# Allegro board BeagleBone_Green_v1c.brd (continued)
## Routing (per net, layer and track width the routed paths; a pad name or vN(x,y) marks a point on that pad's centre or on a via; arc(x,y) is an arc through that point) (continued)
LCD_DATA8: length 23.7
  TOP w0.121: U5.U1 52.71,35.21 53.34,35.84 53.34,36.58 v1(53.59,36.83)
  LYR3 w0.133: v1(53.59,36.83) 53.9,36.83 54.48,37.41 56.08,37.41 61.34,42.67 63.37,42.67 63.63,42.93 63.63,44.16 63.93,44.46 63.93,45.67 v1(63.86,45.75)
  BOTTOM w0.121: R87.1 64.14,45.47 v1(63.86,45.75) 63.63,45.97 63.63,46.99 R62.2 64.14,48.9 P8.37
LCD_DATA9: length 26.9
  TOP w0.121: v1(53.59,37.47) 53.09,36.96 53.09,35.97 52.73,35.61 52.36,35.61 51.96,35.21 U5.U2
  LYR3 w0.133: v1(63.53,44.63) 63,44.11 61.31,44.11 60.6,43.4 60.6,42.32 56.01,37.72 54.23,37.72 53.98,37.47 v1(53.59,37.47)
  BOTTOM w0.121: P8.38 64.26,51.56 64.26,49.5 62.87,48.11 R61.2 63.37,46.99 63.37,45.59 R86.1 63.32,44.63 v1(63.53,44.63)
LCD_DATA10: length 26.5
  TOP w0.121: v1(52.22,37.52) 52.12,37.41 52.12,35.85 51.88,35.61 51.32,35.61 U5.U3
  LYR3 w0.133: v1(52.22,37.52) 52.69,37.99 55.89,37.99 60.33,42.42 60.33,44.32 v1(61.75,45.75)
  BOTTOM w0.121: R85.1 61.98,45.52 v1(61.75,45.75) 61.47,46.02 61.47,46.99 R60.2 61.98,47.75 63.88,49.66 63.88,51.69 P8.36
LCD_DATA11: length 25
  TOP w0.121: v1(56.26,48.39) R84.1 ; v1(51.18,37.21) 50.52,36.55 50.52,35.61 U5.U4
  LYR3 w0.133: v1(56.26,48.39) 55.63,47.75 54.23,47.75 51.87,45.39 51.87,38.96 51.41,38.51 51.41,37.44 v1(51.18,37.21)
  BOTTOM w0.121: P8.34 60.07,52.7 58.67,51.31 57.28,51.31 56.77,50.8 56.77,48.9 v1(56.26,48.39) R84.1
LCD_DATA12: length 24.3
  TOP w0.121: v1(52.2,38.2) 51.72,37.72 U5.V2
  LYR3 w0.133: v1(61.09,45.8) 60.45,45.16 59.16,45.16 58.95,44.96 53.09,44.96 52.59,44.46 52.59,38.6 v1(52.2,38.2)
  BOTTOM w0.121: P8.35 60.71,48.01 R58.2 61.21,46.99 61.21,45.92 v1(61.09,45.8) 60.71,45.42 R83.1
LCD_DATA13: length 22.5
  TOP w0.121: v1(51.23,36.55) 50.92,36.24 U5.V3
  LYR3 w0.133: v1(59.39,45.77) 59,45.77 58.44,45.21 52.83,45.21 52.12,44.5 52.12,38.73 51.74,38.35 51.74,37.06 v1(51.23,36.55)
  BOTTOM w0.121: R82.1 59.82,45.34 v1(59.39,45.77) 59.31,45.85 59.31,46.99 R57.2 59.82,49.66 P8.33
LCD_DATA14: length 19.3
  TOP w0.121: P8.31 56.77,49.15 53.98,49.15 53.59,48.77 53.59,48.13 R56.2 52.58,47.12 52.58,45.21 52.96,44.83 R81.1 52.32,43.81 52.32,43.05 51.94,42.67 51.94,38.86 50.12,37.04 U5.V4
LCD_DATA15: length 24.4
  TOP w0.121: v1(49.72,34.81) U5.T5 ; v1(54.23,48.51) 53.98,48.26 R80.1
  LYR3 w0.133: v1(49.72,34.81) 49.72,36.77 50.8,37.85 50.8,43.31 51.63,44.14 51.63,45.49 54.23,48.08 v1(54.23,48.51)
  BOTTOM w0.121: P8.32 57.66,52.7 56.52,51.56 56.52,49.66 56.01,49.15 54.86,49.15 v1(54.23,48.51) R55.2
LCD_DE: length 15.3
  TOP w0.121: 55.24,52.7 53.85,51.31 52.07,51.31 51.56,50.8 51.56,48.51 50.42,47.37 50.42,45.09 50.8,44.7 50.8,42.93 50.16,42.29 R48.2
LCD_HSYNC: length 11.5
  TOP w0.121: 55.24,50.16 54.1,50.16 52.14,48.2 52.14,46.04 52.07,45.97 52.07,43.18 51.44,42.55 R47.2
LCD_PCLK: length 9.3
  TOP w0.121: P8.28 51.18,51.18 51.18,48.67 50.16,47.65 R45.2
LCD_VSYNC: length 6.6
  TOP w0.121: R46.2 51.44,45.59 51.05,45.97 51.05,47.5 52.7,49.15 P8.27
LCDDE: length 6.9
  TOP w0.121: R48.1 v1(50.16,39.12) ; v1(48.92,34.01) U5.R6
  LYR3 w0.121: 49.32,35.18 49.32,34.41 v1(48.92,34.01)
  LYR3 w0.133: v1(50.16,39.12) 49.4,38.35 49.4,37.72 49.32,37.64 49.32,35.18
LCDPCLK: length 7.8
  TOP w0.121: R45.1 50.16,42.8 49.66,42.29 49.66,37.55 49.32,37.21 U5.V5
LCDVHYNC: length 7.1
  TOP w0.121: v1(51.44,39.12) R47.1 ; v1(49.72,34.01) U5.R5
  LYR3 w0.121: v1(49.72,34.01) 50.12,34.41 50.12,35.13
  LYR3 w0.133: 50.12,35.13 50.12,36.79 51.08,37.74 51.08,38.76 v1(51.44,39.12)
LCDVSYNC: length 9.1
  TOP w0.121: R46.1 51.44,42.93 50.71,42.21 50.71,38.01 49.72,37.02 49.72,35.61 U5.U5
LDO_PGOOD: length 35.6
  TOP w0.121: U2.46 21.46,18.99 v1(20.83,19.62) ; U5.B5 v1(49.72,22.81)
  LYR3 w0.133: v1(49.72,22.81) 49.72,20.51 49.4,20.19 47.35,20.19 46.35,19.2 38.18,19.2 37.29,20.09 34.9,20.09 33.53,21.46 27.05,21.46 25.91,20.32 21.53,20.32 v1(20.83,19.62)
LEDAA: length 6.3
  TOP w0.381: D2.2 6.48,49.02 6.86,48.64 6.86,48.26 7.37,47.75 11.18,47.75 R72.2
LEDAC: length 17.4
  TOP w0.121: v1(18.54,45.59) 19.05,45.59 19.29,45.35 Q1.6 ; D2.1 4.13,48.7 4.7,48.13 v1(6.22,48.13)
  LYR3 w0.133: v1(18.54,45.59) 16.64,47.5 6.86,47.5 v1(6.22,48.13)
LEDBA: length 5.7
  TOP w0.381: D3.2 6.29,46.74 R73.2
LEDBC: length 22.1
  TOP w0.121: Q1.3 20.59,43.58 20.83,43.81 v1(21.21,43.81) ; v1(3.3,48.26) 4.13,47.43 D3.1
  LYR3 w0.133: v1(3.3,48.26) 4.45,47.12 15.11,47.12 18.41,43.81 v1(21.21,43.81)
LEDCA: length 5.9
  TOP w0.381: R74.2 7.62,45.85 6.73,44.96 D4.2
LEDCC: length 13.8
  TOP w0.121: v1(15.62,45.59) 16,45.21 16.51,45.21 16.62,45.1 Q2.6 ; D4.1 4.13,45.02 v1(5.33,46.23)
  LYR3 w0.133: v1(15.62,45.59) 14.99,46.23 v1(5.33,46.23)
LEDDA: length 6.4
  TOP w0.381: D5.2 5.97,43.18 7.87,45.09 11.18,45.09 R71.2
LEDDC: length 19.1
  TOP w0.121: D5.1 4.06,43.18 v1(3.3,43.94) ; v1(18.54,42.47) 18.47,42.47 17.92,43.01 Q2.3
  LYR3 w0.133: v1(3.3,43.94) 4.47,45.11 15.9,45.11 v1(18.54,42.47)
MDIO_CLK: length 14.5
  TOP w0.121: U14.17 26.83,34.17 26.95,34.29 28.7,34.29 28.83,34.16 32,34.16 32.51,34.67 33.4,34.67 35.31,32.77 35.69,32.77 36.7,31.75 37.72,31.75 38.35,31.11 38.82,31.11 U5.M18
MDIO_DATA: length 15
  TOP w0.121: U5.M17 39.32,30.81 38.28,30.81 37.59,31.5 36.58,31.5 35.56,32.51 35.18,32.51 33.38,34.31 32.66,34.31 32.26,33.91 32.26,33.46 31.97,33.18 30.45,33.18 R119.2 29.34,33.66 28.83,33.15 28.32,33.15 28.04,32.87 U14.16
MII1_COL: length 24.2
  TOP w0.121: v1(40.12,27.61) U5.H16
  LYR3 w0.133: v1(31.75,26.04) 31.11,26.04 30.99,25.91 30.99,25.27 30.86,25.15 29.84,25.15 29.72,25.27 29.72,26.42 29.84,26.54 32.38,26.54 32.51,26.67 32.51,27.81 32.64,27.94 39.79,27.94 v1(40.12,27.61)
  BOTTOM w0.121: R138.1 31.43,32.26 31.84,32.26 32.15,31.95 32.15,30.84 32.51,30.48 32.51,26.8 v1(31.75,26.04)
MII1_CRS_DV: length 25.6
  TOP w0.121: v1(36.83,28.41) 39.32,28.41 U5.H17 ; R139.1 v1(31.75,32.7)
  BOTTOM w0.121: v1(31.75,32.7) 31.75,33.05 31.85,33.15 32.3,33.15 32.4,33.05 32.4,31.09 32.5,30.99 34.95,30.99 35.05,30.89 35.05,30.77 34.95,30.67 32.96,30.67 32.86,30.57 32.86,30.45 32.96,30.35 35.81,30.35 36.07,30.1 36.07,24.49 36.17,24.38 36.33,24.38 36.43,24.49 36.43,28.01 v1(36.83,28.41)
MII1_REFCLK: length 18.5
  TOP w0.121: R28.2 33.78,27.43 33.91,27.3 34.98,27.3 35.08,27.2 35.08,27.03 34.98,26.92 33.86,26.92 33.78,26.85 33.78,26.62 33.86,26.54 34.98,26.54 35.05,26.47 35.05,26.24 34.98,26.16 33.86,26.16 33.78,26.09 33.78,25.86 33.91,25.73 34.21,25.73 34.3,25.64 34.3,25.47 34.17,25.35 33.88,25.35 33.78,25.25 33.78,24.97 33.71,24.89 32.59,24.89 32.51,24.97 32.51,25.2 32.59,25.27 33.32,25.27 33.4,25.35 33.4,25.58 33.32,25.65 32.59,25.65 32.51,25.73 32.51,25.94 32.59,26.02 33.32,26.02 33.42,26.12 33.42,26.85 33.3,26.97 32.68,26.97 32.46,26.75 32.46,26.62 32.33,26.49 32.2,26.49 32.11,26.58 32.11,26.95 32,27.05 31.81,27.05 v1(31.75,26.99) 31.69,26.92 R124.1
  BOTTOM w0.121: v1(31.75,26.99) 31.75,26.8 R140.1
MII1_RXCLK: length 23.8
  TOP w0.121: U5.L18 38.3,30.41 37.47,31.24 36.45,31.24 35.43,32.26 35.05,32.26 33.78,33.53 33.53,33.53 33.42,33.42 33.42,33 33.29,32.87 32.26,32.87 32.15,32.77 32.15,32.63 32.28,32.51 32.66,32.51 32.77,32.4 32.77,30.58 32.87,30.48 32.98,30.48 33.08,30.58 33.08,31.78 33.19,31.88 33.36,31.88 33.46,31.78 33.46,29.34 33.34,29.21 32.64,29.21 32.51,29.34 32.51,30.04 32.19,30.35 31.85,30.35 31.75,30.45 v1(31.75,30.8)
  BOTTOM w0.121: v1(31.75,30.8) 32.26,30.29 32.26,27.81 31.88,27.43 31.11,27.43 30.99,27.3 R131.1
MII1_RXD0: length 24.3
  TOP w0.121: v1(31.75,31.75) 31.75,31.56 R128.1 ; U5.M16 40.12,31.61 v1(39.32,31.61)
  LYR3 w0.133: v1(31.75,31.75) 30.96,31.75 30.86,31.85 30.86,35.97 30.96,36.07 32.28,36.07 32.38,35.97 32.38,35.15 32.28,35.05 31.37,35.05 31.24,34.92 31.24,34.29 31.37,34.16 32.28,34.16 32.38,34.06 32.38,33.25 32.28,33.15 31.37,33.15 31.24,33.02 31.24,32.42 31.37,32.3 32.36,32.3 32.64,32.02 38.91,32.02 v1(39.32,31.61)
MII1_RXD1: length 24.6
  TOP w0.121: R127.1 31.24,30.1 31.5,30.1 v1(31.75,29.84) ; U5.L15 v1(40.92,30.01)
  LYR3 w0.121: v1(40.92,30.01) 40.52,29.61 39.75,29.61
  LYR3 w0.133: v1(31.75,29.84) 31.5,30.1 30.96,30.1 30.1,30.96 30.1,31.88 29.97,32 29.74,32 29.62,31.88 29.62,30.71 30.99,29.34 31.88,29.34 32.16,29.62 32.16,30.12 32.89,30.86 32.89,31.14 32.99,31.24 33.17,31.24 33.27,31.14 33.27,30.71 33.38,30.61 33.55,30.61 33.66,30.71 33.66,31.14 33.76,31.24 33.93,31.24 34.04,31.14 34.04,30.71 34.14,30.61 34.32,30.61 34.42,30.71 34.42,31.14 34.52,31.24 34.7,31.24 34.8,31.14 34.8,30.71 34.9,30.61 35.08,30.61 35.15,30.68 35.15,31.14 35.26,31.24 36.2,31.24 36.32,31.11 36.32,30.51 36.42,30.4 37.11,30.4 37.24,30.53 37.24,30.99 37.33,31.08 37.6,31.08 39.07,29.61 39.75,29.61
MII1_RXD2: length 24.2
  TOP w0.121: R126.1 30.99,29.24 31.09,29.34 31.39,29.34 31.5,29.24 31.5,28.99 31.6,28.89 31.78,28.89 31.88,28.99 31.88,29.36 31.98,29.46 32.16,29.46 32.26,29.36 32.26,28.99 32.36,28.89 33.66,28.89 33.78,29.02 33.78,32.03 33.68,32.13 33.12,32.13 33.02,32.23 33.02,32.41 33.12,32.51 33.55,32.51 33.66,32.61 33.66,32.92 33.76,33.02 33.94,33.02 34.69,32.27 34.69,30.85 34.8,30.73 34.96,30.73 35.07,30.85 35.07,31.91 35.17,32.01 35.31,32.01 35.58,31.74 35.58,31.36 35.68,31.26 36.07,31.26 36.21,31.11 36.21,30.94 36.07,30.8 35.85,30.8 v1(35.84,30.81) ; U5.L16 v1(40.92,30.81)
  BOTTOM w0.121: v1(40.92,30.81) 40.92,30.56 40.77,30.41 39.95,30.41 39.37,29.83 39.37,29.59 39.12,29.34 37.21,29.34 37.01,29.54 36.47,29.54 36.35,29.67 36.35,30.81 36.23,30.93 35.96,30.93 v1(35.84,30.81)
MII1_RXD3: length 24.2
  TOP w0.121: U5.L17 39.72,30.2 39.54,30.01 37.69,30.01 37.59,30.11 37.59,30.76 37.49,30.86 37.31,30.86 37.23,30.78 37.23,30.2 37.13,30.1 36.86,30.1 36.6,30.35 36.35,30.35 36.09,30.1 35.94,30.1 35.69,30.35 34.9,30.35 34.8,30.25 34.8,28.93 34.9,28.83 35.08,28.83 35.18,28.93 35.18,29.17 35.3,29.29 35.38,29.29 35.47,29.2 35.47,28.93 35.57,28.83 35.76,28.83 35.86,28.93 35.86,29.34 35.96,29.45 36.09,29.45 36.18,29.36 36.18,28.66 36.09,28.57 34.52,28.57 34.42,28.68 34.42,32.16 34.32,32.26 34.14,32.26 34.04,32.16 34.04,28.7 33.91,28.57 31.62,28.57 R125.1
MII1_RXDV: length 25.6
  TOP w0.121: U5.J17 v1(40.12,29.21) ; v1(22.66,35.79) 21.95,35.79 R129.1
  LYR3 w0.133: v1(22.66,35.79) 22.78,35.66 22.78,33.91 23.95,32.74 25.37,32.74 28.75,29.36 29.64,29.36 30.33,28.68 31.98,28.68 32.63,29.32 32.63,29.86 32.81,30.05 34.7,30.05 35.33,29.41 35.71,29.41 36.37,30.07 38.23,30.07 38.96,29.34 39.99,29.34 v1(40.12,29.21)
MII1_RXERR: length 24.5
  TOP w0.121: R133.1 30.99,32.14 31.08,32.23 31.4,32.23 31.43,32.26 32.29,32.26 32.39,32.16 32.39,31.76 32.16,31.52 32.16,30.84 33.02,29.97 33.02,29.65 v1(33.03,29.64) ; U5.J15 v1(40.92,29.21)
  LYR3 w0.121: v1(40.92,29.21) 40.52,28.81 39.86,28.81
  LYR3 w0.133: 39.86,28.81 39.47,28.81 39.3,28.98 39.01,28.98 38.91,28.88 38.91,28.57 38.82,28.48 38.55,28.48 38.46,28.57 38.46,29.44 38.33,29.57 38.13,29.57 38.05,29.49 38.05,28.55 37.95,28.46 37.76,28.46 37.59,28.63 37.59,29.39 37.21,29.77 36.55,29.77 36.14,29.36 36.14,28.61 36.01,28.47 35.74,28.47 35.67,28.55 35.67,29.01 35.57,29.11 35.38,29.11 35.28,29.01 35.28,28.57 35.18,28.47 34.96,28.47 34.83,28.61 34.83,29.57 34.71,29.69 34.52,29.69 34.42,29.59 34.42,28.6 34.32,28.5 34.09,28.5 33.96,28.64 33.96,29.62 33.81,29.77 33.63,29.77 33.5,29.64 33.5,28.55 33.41,28.46 33.09,28.46 32.99,28.55 32.99,29.6 v1(33.03,29.64)
MII1_TXCLK: length 22.8
  TOP w0.121: U5.K18 37.47,29.61 37.26,29.82 35.74,29.82 35.64,29.92 v1(35.55,29.92)
  LYR3 w0.133: v1(35.55,29.92) 35.15,30.33 32.72,30.33 32.39,30 32.39,29.5 31.88,28.98 30.84,28.98 29.49,30.33 28.35,30.33 27.74,30.94 27.74,31.34 27.38,31.7 26.85,31.7 26.72,31.83 26.72,32.13 26.8,32.21 27.64,32.21 27.82,32.39 27.82,32.58 27.64,32.77 27.33,32.77 27.23,32.87 27.23,33.12 27.33,33.22 28.19,33.22 v1(28.57,33.6)
  BOTTOM w0.121: v1(28.57,33.6) 28.57,34.62 29.01,35.05 30.48,35.05 R134.1
MII1_TXD0: length 28
  TOP w0.121: v1(24.13,34.61) 24.33,34.41 U14.22 ; U5.K17 39.32,29.21 37.47,29.21 37.19,29.48 36.53,29.48 36.43,29.38 36.43,28.4 36.35,28.32 32.26,28.32 32.15,28.21 32.15,27.61 32,27.46 28.92,27.46 v1(28.45,27.94)
  LYR4 w0.133: v1(28.45,27.94) 27.94,28.45 27.69,28.45 27.33,28.8 27.33,30.23 27.2,30.35 26.7,30.35 26.62,30.43 26.62,30.86 26.72,30.96 27.18,30.96 27.33,31.11 27.33,31.6 27.18,31.75 25.93,31.75 25.81,31.88 25.81,32.2 25.94,32.33 26.52,32.33 26.61,32.42 26.61,32.68 26.26,33.02 24.82,33.02 24.74,33.1 24.74,33.45 24.84,33.55 25.27,33.55 25.39,33.67 25.39,33.9 25.25,34.04 24.7,34.04 v1(24.13,34.61)
MII1_TXD1: length 28
  TOP w0.121: U14.23 23.83,34.27 v1(23.5,34.61) ; v1(40.12,30.01) U5.K16
  LYR3 w0.133: v1(23.5,34.61) 24.07,34.04 25.78,34.04 25.94,33.88 25.94,33.69 25.78,33.53 24.14,33.53 24,33.39 24,33.21 24.1,33.11 26.81,33.11 27.1,33.4 27.1,33.86 27.41,34.16 29.84,34.16 30.35,33.66 30.35,31.11 31.08,30.39 31.92,30.39 32.16,30.63 32.16,30.96 32.69,31.5 37.62,31.5 39.1,30.01 v1(40.12,30.01)
MII1_TXD2: length 28.1
  TOP w0.121: v1(28.45,35.56) 28.19,35.31 23.56,35.31 23.1,34.84 23.1,34.37 23.33,34.14 U14.24 ; U5.K15 v1(41.72,30.01)
  LYR3 w0.121: v1(41.72,30.01) 41.72,30.01 41.32,30.41 39.88,30.41
  LYR3 w0.133: 39.88,30.41 39.08,30.41 37.74,31.75 32.51,31.75 32.03,31.27 30.71,31.27 30.61,31.37 30.61,36.58 30.48,36.7 28.57,36.7 28.45,36.58 v1(28.45,35.56)
MII1_TXD3: length 28.3
  TOP w0.121: v1(35.56,33.27) 33.78,35.05 31.42,35.05 31.29,34.92 31.29,34.62 31.21,34.53 30.79,34.53 30.73,34.59 30.73,35.86 30.63,35.97 30.35,35.97 30.25,35.86 30.25,34.67 30.12,34.54 29.84,34.54 29.72,34.66 29.72,35.74 29.13,36.32 25.35,36.32 24.71,35.69 23.24,35.69 22.38,34.82 22.38,34.32 22.1,34.04 22.1,33.06 22.29,32.87 U14.25 ; v1(36.83,29.08) 36.83,29.06 37.08,28.81 U5.J18
  LYR4 w0.133: v1(36.83,29.08) 36.32,29.59 36.32,32.51 v1(35.56,33.27)
MII1_TXEN: length 28.5
  TOP w0.121: v1(40.12,28.41) U5.J16 ; v1(24.83,34.61) U14.21
  LYR3 w0.133: v1(28.45,28.89) 28.42,28.87 28.42,28.48 28.56,28.35 29.46,28.35 29.67,28.55 30.02,28.55 30.15,28.42 30.15,27 30.24,26.91 30.46,26.91 30.63,27.08 30.63,28.22 30.76,28.35 31.01,28.35 31.19,28.17 31.19,27.57 31.32,27.43 32.03,27.43 32.26,27.66 32.26,28.55 32.41,28.7 32.61,28.7 32.74,28.57 32.74,28.35 32.89,28.19 36.25,28.19 36.4,28.35 36.4,29.26 36.65,29.51 37.01,29.51 37.34,29.18 37.34,28.51 37.66,28.19 37.99,28.19 37.99,28.2 39.9,28.2 39.9,28.19 v1(40.12,28.41)
  LYR4 w0.133: v1(28.45,28.89) 28,28.89 27.76,29.13 27.76,31.95 25.11,34.61 v1(24.83,34.61)
MMC0_CD: length 80.4
  TOP w0.121: v1(40.92,23.61) U5.C15
  LYR3 w0.133: v1(70.1,42.8) 70.1,35.59 71.07,34.62 71.07,19.63 66.73,15.29 55.22,15.29 54.51,16 54.51,17.83 53.21,19.13 52.4,19.13 51.71,19.81 47.4,19.81 46.43,18.85 35.33,18.85 v1(35.15,18.67)
  BOTTOM w0.121: v1(40.92,23.61) 40.52,23.21 40.52,21.84 39.53,20.85 36.09,20.85 35.42,20.18 35.42,19.31 35.15,19.05 v1(35.15,18.67) 34.67,18.67 34.61,18.73 P2.19 ; P10.10 69.98,43.69 69.92,43.63 69.86,43.63 69.47,43.24 R157.1 69.72,43.18 v1(70.1,42.8)
MMC0_CLKO: length 81.6
  TOP w0.121: v1(31.75,20.32) 32.84,21.41 32.84,23.63 35.24,26.04 37.08,26.04 38.66,27.61 39.32,27.61 U5.G17
  LYR3 w0.133: v1(31.75,20.32) 31.74,20.31 31.74,19.29 33.98,17.06 38.55,17.06 39.27,17.78 42.48,17.78 44.99,15.27 46.05,15.27 47.47,13.84 47.47,11.91 48.26,11.12 52.8,11.12 55.83,14.15 68.08,14.15 72.62,18.68 72.62,22.9 77.68,27.97 79.78,27.97 v1(80.24,27.51)
  BOTTOM w0.121: v1(80.24,27.51) 80.67,27.94 R152.2 82.58,29.62 83.21,29.62 83.7,30.1 P10.5
MMC0_CMD: length 92.7
  TOP w0.121: U5.G18 38.64,27.21 37.21,25.78 35.34,25.78 33.15,23.59 33.15,21.08 v1(32.38,20.32) ; R151.2 81.41,42.93 v1(82.17,43.69)
  LYR3 w0.133: v1(82.17,43.69) 82.17,43.56 81.66,43.05 81.66,38.48 72.16,28.98 72.16,18.56 68.05,14.45 55.7,14.45 52.6,11.35 48.36,11.35 47.75,11.96 47.75,14.45 45.14,17.07 44.25,17.07 43.3,18.01 39.18,18.01 38.55,17.39 38.55,17.39 38.45,17.29 34.08,17.29 31.98,19.39 31.98,19.91 v1(32.38,20.32)
  BOTTOM w0.121: v1(82.17,43.69) 83,44.51 P10.3
MMC0_DAT0: length 69.6
  TOP w0.121: v1(40.12,26.81) U5.G16
  LYR3 w0.133: v1(78.99,27.56) 78.23,26.8 77.43,26.8 73.28,22.64 73.28,18.68 68.21,13.61 56.11,13.61 53.14,10.65 48.07,10.65 46.86,11.85 46.86,13.66 45.91,14.61 44.99,14.61 42.68,16.92 40.28,16.92 40.13,16.76 v1(39.7,16.76)
  LYR4 w0.133: v1(40.12,26.81) 39.92,26.81 37.82,24.71 37.82,21.59 38.28,21.13 38.28,18.11 39.62,16.76 v1(39.7,16.76)
  BOTTOM w0.121: v1(78.99,27.56) 79.25,27.56 R153.2 80.52,28.83 81.03,28.83 82.3,30.1 P10.7
MMC0_DAT1: length 68.5
  TOP w0.121: v1(40.92,26.81) U5.G15
  LYR3 w0.133: v1(39.71,17.37) 42.55,17.37 45,14.92 45.93,14.92 47.12,13.73 47.12,11.93 48.17,10.88 53,10.88 55.98,13.87 68.14,13.87 73,18.73 73,22.71 v1(77.72,27.43)
  LYR4 w0.121: 38.07,22.1 38.07,21.88 38.11,21.84 ; v1(39.71,17.37) 38.58,18.5 38.58,21.37 ; 39.74,26.19 39.95,26.41 40.52,26.41 v1(40.92,26.81)
  LYR4 w0.133: 38.58,21.37 38.11,21.84 ; 38.07,22.1 38.07,24.53 39.74,26.19
  BOTTOM w0.121: P10.8 81.6,30.03 80.77,29.21 79.63,29.21 R154.2 78.23,27.94 v1(77.72,27.43)
MMC0_DAT2: length 87.2
  TOP w0.121: R150.2 79.63,42.8 v1(80.52,43.69) ; v1(33.02,19.56) 33.15,19.56 33.42,19.83 33.42,23.51 35.44,25.53 37.34,25.53 38.22,26.41 U5.F18
  LYR3 w0.133: v1(33.02,19.56) 34.57,18.01 35.28,18.01 35.81,18.54 43.56,18.54 44.15,17.96 45.97,17.96 47.45,19.43 51.64,19.43 52.25,18.82 53.11,18.82 54.23,17.7 54.23,15.8 55.04,14.99 66.85,14.99 71.53,19.66 71.53,29.06 80.8,38.33 80.8,43.28 80.52,43.56 v1(80.52,43.69)
  BOTTOM w0.121: P10.1 81.6,44.64 81.15,44.2 81.03,44.2 v1(80.52,43.69)
MMC0_DAT3: length 90.6
  TOP w0.121: U5.F17 39.32,26.01 38.19,26.01 37.47,25.29 35.55,25.29 33.78,23.52 33.78,19.56 33.27,19.05 32.89,19.05 v1(32.38,19.56) ; v1(81.28,43.69) 80.52,42.93 R155.2
  LYR3 w0.133: v1(32.38,19.56) 34.32,17.63 38.46,17.63 39.08,18.25 43.45,18.25 44.35,17.35 45.92,17.35 47.75,19.18 51.44,19.18 52.7,17.91 53.52,17.91 53.98,17.45 53.98,15.65 54.94,14.68 66.88,14.68 71.86,19.66 71.86,29.01 81.28,38.43 v1(81.28,43.69)
  BOTTOM w0.121: P10.2 82.3,44.58 81.41,43.69 v1(81.28,43.69)
MMC1_CLK: length 41.5
  TOP w0.121: U5.U9 46.52,35.61 46.52,35.98 46.52,35.98 46.52,36.17 46.67,36.32 46.67,44.39 45.85,45.21 45.85,49.4 P8.21
  TOP w0.203: v1(28.09,42.49) 28.07,42.47 27.78,42.47 U13.M6
  LYR4 w0.133: v1(28.09,42.49) 28.26,42.49 29.43,41.33 34.49,41.33 36.91,43.74 36.91,44.65 40.01,47.75 43.88,47.75 45.09,48.96 P8.21
  BOTTOM w0.121: R110.2 P8.21
MMC1_CMD: length 43.6
  TOP w0.121: P8.20 43.81,51.44 43.81,49.53 45.59,47.75 45.59,44.96 46.42,44.13 46.42,36.52 46.12,36.21 U5.V9
  TOP w0.203: U13.M5 27.63,43.12 28.03,43.12 v1(28.09,43.05)
  LYR4 w0.133: v1(42.55,48.26) 40.01,48.26 36.65,44.91 36.65,43.84 34.39,41.58 29.68,41.58 28.2,43.05 v1(28.09,43.05)
  BOTTOM w0.121: R109.2 v1(42.55,48.26) 41.4,49.4 41.4,51.56 P8.20
MMC1_DAT0: length 35.5
  TOP w0.121: v1(48.9,48.26) 48.39,47.75 48.39,45.47 47.75,44.83 47.75,39.24 47.76,39.24 47.76,39.14 48.26,38.64 48.26,36.58 48.12,36.44 48.12,35.61 U5.U7 ; v1(38.1,44.96) 37.11,45.95 35.2,45.95 33.42,44.16 U13.A3
  LYR4 w0.133: v1(48.9,48.26) 47.37,46.74 41.27,46.74 39.5,44.96 v1(38.1,44.96)
  BOTTOM w0.121: R101.2 v1(48.9,48.26) 48.9,48.9 P8.25
MMC1_DAT1: length 39.5
  TOP w0.121: P8.24 48.77,51.56 48.77,49.4 48.13,48.77 48.13,45.59 47.5,44.96 47.5,38.99 48.01,38.48 48.01,36.7 47.72,36.42 U5.V7 ; U13.A4 33.65,43.66 34.55,44.56 36.92,44.56 37.03,44.45 38.35,44.45 38.73,44.83 v1(38.73,45.72)
  LYR4 w0.133: v1(46.35,48.26) 45.34,47.24 40.26,47.24 v1(38.73,45.72)
  BOTTOM w0.121: R102.2 v1(46.35,48.26) 46.35,51.44 P8.24
MMC1_DAT2: length 41.4
  TOP w0.121: v1(47.32,34.01) U5.R8 ; U13.A5 34.35,43.16 34.62,43.43 34.62,43.84 34.87,44.09 v1(35.56,44.09)
  LYR3 w0.121: 46.92,35.05 46.92,34.41 v1(47.32,34.01)
  LYR3 w0.133: 46.92,35.05 46.92,35.12 46.23,35.81 46.23,39.8 44.2,41.83 44.2,43.69 42.67,45.21 38.48,45.21 38.23,45.47 36.93,45.47 v1(35.56,44.09)
  LYR4 w0.133: v1(26.04,48.26) 26.04,47.88 27.69,46.23 29.13,46.23 33.3,42.06 34.29,42.06 35.56,43.33 v1(35.56,44.09)
  BOTTOM w0.121: P8.5 26.04,48.9 v1(26.04,48.26) R103.2
MMC1_DAT3: length 38.9
  TOP w0.076: U13.B2 32.6,44.68 32.84,44.92 32.84,45.37 32.92,45.44 33.2,45.72
  TOP w0.121: v1(33.91,46.52) 33.91,46.43 33.2,45.72 ; v1(47.32,34.81) U5.T8
  LYR3 w0.133: v1(47.32,34.81) 47.32,35.23 46.49,36.06 46.49,39.92 44.45,41.96 44.45,43.94 43.05,45.34 43.05,45.97 42.77,46.25 34.18,46.25 v1(33.91,46.52)
  LYR4 w0.133: v1(27.3,48.26) 28.19,47.37 30.38,47.37 31.23,46.52 v1(33.91,46.52)
  BOTTOM w0.121: R104.2 v1(27.3,48.26) 26.04,49.53 26.04,51.44 P8.6
MMC1_DAT4: length 38.1
  TOP w0.076: 33.49,44.59 33.31,44.41 33.2,44.41 32.86,44.41 32.61,44.16 U13.B3
  TOP w0.121: U5.U8 47.32,35.61 47.32,36.4 47.75,36.83 47.75,38.35 47.24,38.86 47.24,44.7 47.12,44.83 47.12,48.39 47.62,48.9 P8.23 ; v1(34.59,46.66) 34.59,45.69 33.49,44.59
  LYR4 w0.133: P8.23 46.61,51.18 39.24,51.18 38.73,50.67 38.73,49.4 35.99,46.66 v1(34.59,46.66)
  BOTTOM w0.121: R105.2 P8.23
MMC1_DAT5: length 36.7
  TOP w0.076: 33.4,43.91 32.87,43.91 32.61,43.66 U13.B4
  TOP w0.121: P8.22 46.35,51.44 46.35,49.66 46.86,49.15 46.86,44.7 46.92,44.65 U5.V8 ; v1(35.51,45.52) 35.48,45.49 35.1,45.49 33.53,43.92 33.53,43.92 33.52,43.91 33.4,43.91
  LYR4 w0.133: v1(43.81,48.26) 43.41,48.67 39.9,48.67 36.73,45.49 35.53,45.49 v1(35.51,45.52)
  BOTTOM w0.121: R106.2 v1(43.81,48.26) 43.81,51.44 P8.22
MMC1_DAT6: length 40.4
  TOP w0.076: U13.B5 32.61,43.16 32.86,43.41 33.48,43.41
  TOP w0.121: 33.48,43.41 33.66,43.41 33.78,43.41 33.98,43.6 34.15,43.6 v1(34.16,43.59) ; v1(46.52,34.01) U5.R9
  LYR3 w0.133: v1(46.52,34.01) 44.7,35.83 44.7,40.56 43.69,41.58 43.69,43.31 42.67,44.32 38.48,44.32 37.29,43.13 34.62,43.13 v1(34.16,43.59)
  LYR4 w0.133: v1(23.5,48.26) 24.26,49.02 26.54,49.02 26.9,48.67 26.9,48.03 27.94,46.99 29.08,46.99 32.66,43.41 33.78,43.41 33.97,43.59 34.16,43.59 v1(34.16,43.59)
  BOTTOM w0.121: P8.3 23.5,48.9 v1(23.5,48.26) R107.2
MMC1_DAT7: length 42.9
  TOP w0.076: U13.B6 32.85,42.91 33.41,42.91 33.42,42.9
  TOP w0.121: v1(46.52,34.81) U5.T9 ; 33.42,42.9 34.49,42.9 35.03,43.43 v1(35.03,43.64)
  LYR3 w0.133: v1(46.52,34.81) 45.09,36.25 45.09,40.51 43.94,41.66 43.94,43.56 42.67,44.83 38.61,44.83 37.34,43.56 35.1,43.56 v1(35.03,43.64)
  LYR4 w0.133: v1(35.03,43.64) 34.44,43.05 32.64,43.05 29.08,46.61 27.81,46.61 26.54,47.88 26.54,48.39 26.26,48.67 25.17,48.67 v1(24.77,48.26)
  BOTTOM w0.121: P8.4 23.5,51.44 23.5,49.53 v1(24.77,48.26) R108.2
MODE2: length 3.9
  TOP w0.121: v1(28.45,32.7) 28.11,32.37 U14.15
  BOTTOM w0.121: v1(28.45,32.7) 28.66,32.7 28.81,32.85 28.81,32.87 29.04,33.1 29.06,33.1 29.62,33.66 R113.1 R138.2
OSC1_IN: length 8.2
  TOP w0.121: Y1.1 49.93,16.72 50.16,16.95 v1(50.16,17.78) 50.16,18.41 49.53,19.05 49.53,20.45 49.66,20.57 49.66,21.27 U5.A6
  BOTTOM w0.121: v1(50.16,17.78) 50.48,17.46 C21.2
OSC1_OUT: length 8.6
  TOP w0.121: U5.A4 50.12,21.89 50.36,21.65 50.36,20.38 50.16,20.19 50.16,19.3 51.05,18.41 51.44,18.41 v1(52.07,17.78) 52.07,16.95 52.31,16.72 Y1.4
  BOTTOM w0.121: v1(52.07,17.78) 51.75,17.46 C22.2
P_BYPASS: length 2.6
  TOP w0.203: U2.47 21.06,18.88 20.83,19.11 20.26,19.11 v1(20.22,19.15)
  BOTTOM w0.381: v1(20.22,19.15) 20.19,19.13 C4.2
P_INT_LDO: length 3.1
  TOP w0.121: U2.48 20.66,18.58 20.57,18.67 19.96,18.67 19.71,18.92 19.71,19.65 20.38,20.32 C3.2
P_L1: length 1
  TOP w0.203: U2.20 23.46,11.18
  vias: v1(22.35,9.91) v1(22.99,9.91)
P_L2: length 0.6
  TOP w0.203: 24.66,11.53 U2.23
  vias: v1(24.64,9.91) v1(25.27,9.91)
P_L3: length 2.9
  BOTTOM w0.381: 28.57,16.7 L3.1 29.21,16.7 v1(29.21,17.4) v1(28.57,17.4) 28.57,16.7
PHY_VDDCR: length 4.1
  TOP w0.254: v1(26.23,27.69) 26.21,27.69 25.83,28.06 U14.6
  BOTTOM w0.381: C136.1 C134.1 27.18,27.93 26.93,27.69 v1(26.23,27.69)
PHY_XTAL1: length 6.5
  TOP w0.152: v1(25.43,24.73) 25.44,24.71 26.7,24.71 26.98,25 Y3.1
  BOTTOM w0.121: v1(25.43,24.73) 25.43,24.74 26.77,24.74 27.05,25.02 C143.1 R141.2 25.91,26.04 R142.1
PHY_XTAL2: length 3.5
  TOP w0.121: U14.4 24.83,27.94 24.9,27.87 24.9,27.18 v1(24.89,27.18)
  BOTTOM w0.121: R141.1 25.02,25.4 R143.1 25.02,27.05 v1(24.89,27.18)
PHYX: length 3.8
  TOP w0.121: Y3.2 24.32,25.72 v1(24.51,25.91)
  BOTTOM w0.121: R143.2 24,26.29 23.75,26.04 C142.1 23.88,25.27 v1(24.51,25.91)
PMIC_INT: length 23.8
  TOP w0.121: U2.45 21.86,19.35 v1(21.59,19.62) 21.65,19.62 22.35,20.32 R1.2 ; v1(36.96,19.68) 36.96,20.4 37.59,21.03 37.59,21.88 U5.B18
  LYR3 w0.133: v1(21.59,19.62) 22.03,20.07 29.72,20.07 30.48,20.83 33.15,20.83 34.8,19.18 36.45,19.18 v1(36.96,19.68)
PMIC_PGOOD: length 32.9
  TOP w0.121: v1(26.92,12.76) 26.56,13.13 26.56,13.23 26.35,13.44 U2.26 ; U16.2 31.75,10.19 31.32,10.62 30.35,10.62 v1(30.32,10.58) ; v1(40.92,22.81) U5.B15
  LYR3 w0.121: v1(40.92,22.81) 40.52,23.21 39.95,23.21
  LYR3 w0.133: v1(30.32,10.58) 30.3,10.58 30.28,10.57 29.7,10.57 27.5,12.76 v1(26.92,12.76) ; 39.95,23.21 39.34,23.21 38.86,22.73 36.7,22.73 36.2,23.24 36.2,23.37 35.56,24 33.21,24 33.19,23.98 32.85,23.98 32.83,24 31.37,24 30.35,22.99 29.59,22.99 v1(29.34,23.24)
  LYR4 w0.133: v1(29.34,23.24) 28.07,21.97 28.07,13.91 v1(26.92,12.76)
PMIC_POWR_EN: length 65.4
  TOP w0.121: v1(48.92,23.61) U5.C6 ; v1(18.29,14.24) U2.9
  LYR3 w0.133: v1(18.29,14.24) 20.07,12.46 20.07,11.56 22.61,9.02 29.11,9.02 29.67,8.45 34.18,8.45 34.71,8.98 41.47,8.98 41.83,9.35 45.75,9.35 46.43,8.66 56.44,8.66 v1(58.52,10.74)
  LYR4 w0.133: v1(58.52,10.74) 58.47,10.74 57.91,11.3 57.91,16.51 54.99,19.43 54.74,19.43 53.21,20.95 50.42,20.95 48.92,22.45 v1(48.92,23.61)
PROC_A15: length 14
  TOP w0.121: v1(39.73,14.61) 39.55,14.61 38.34,15.81 38.34,20.47 39.34,21.46 40.37,21.46 40.92,22.01 U5.A15
  BOTTOM w0.121: R18.1 41.08,12.57 41.2,12.69 41.2,14 40.59,14.61 v1(39.73,14.61)
PWR_BUT: length 56.3
  TOP w0.121: U2.25 25.93,12.55 26.42,12.06 v1(26.92,12.06) ; S3.2 S3.4 13.51,39.73 17.41,35.83 v1(20.9,35.83)
  LYR4 w0.133: P9.9 28.88,2.87 28.88,10.11 v1(26.92,12.06) 26.52,12.47 26.52,21.82 27.39,22.69 27.39,27.21 23.24,31.36 23.24,33.49 v1(20.9,35.83)
PWR_LEDR: length 2.3
  TOP w0.381: D1.1 2.86,19.88 v1(2.41,19.43)
  BOTTOM w0.381: v1(2.41,19.43) 2.54,19.3 R12.2
RBIAS: length 2.7
  TOP w0.121: U14.32 22.06,29.36 21.91,29.21 21.91,28.89 v1(21.27,28.26)
  BOTTOM w0.121: v1(21.27,28.26) R144.1
RCLKIN: length 8
  TOP w0.121: v1(25.34,27.69) 25.34,27.94 25.33,27.94 U14.5
  BOTTOM w0.121: R140.2 29.87,25.93 28.57,25.93 28.35,26.16 28.35,26.62 28.24,26.72 27.94,26.72 27.81,26.59 27.81,25.95 27.64,25.78 27.22,25.78 27.05,25.95 R142.2 27.05,26.34 26.86,26.53 26.56,26.53 C161.1 25.97,27.05 v1(25.34,27.69)
REFCLKO: length 8
  TOP w0.121: v1(29.21,26.99) 29.27,26.92 R124.2 R118.1 C162.2 28.57,26.42 28.57,27.18 27.81,27.94 26.64,27.94 26.33,28.25 U14.7
  BOTTOM w0.121: R131.2 v1(29.21,26.99)
RXD0/MODE0: length 4.1
  TOP w0.121: U14.11 28.59,30.36 29.02,30.8 v1(29.21,30.8) 29.21,30.48 29.34,30.35 29.84,30.35 29.97,30.48 R128.2
  BOTTOM w0.121: R128.2 v1(29.21,30.8)
RXD1/MODE1: length 4
  TOP w0.121: U14.10 28.89,29.86 29.19,29.86 v1(29.21,29.84) 29.21,29.5 29.34,29.37 29.88,29.37 29.97,29.46 R127.2
  BOTTOM w0.121: R127.2 v1(29.21,29.84)
RXD2/RMIISEL: length 4.1
  TOP w0.121: R126.2 29.97,28.57 29.84,28.45 29.34,28.45 29.21,28.57 v1(29.21,28.89) 28.74,29.36 U14.9
  BOTTOM w0.121: R126.2 v1(29.21,28.89)
RXD3/PHYAD2: length 4.3
  TOP w0.121: R125.2 v1(29.21,27.94) 28.81,28.34 26.96,28.34 26.83,28.47 U14.8
  BOTTOM w0.121: R125.2 v1(29.21,27.94)
RXDV: length 2.7
  TOP w0.121: R129.2 21.62,34.01 21.72,33.91 21.72,32.83 22.18,32.37 U14.26
RXER/PHYAD0: length 4.1
  TOP w0.121: R133.2 29.97,31.37 29.88,31.27 29.34,31.27 29.21,31.4 v1(29.21,31.75) 28.83,31.37 U14.13
  BOTTOM w0.121: R133.2 v1(29.21,31.75)
RXN: length 18.4
  TOP w0.095: P5.2 17.14,33.92 16.89,34.17 16.26,34.17 16,33.92 16,32.64 16.64,32 17.64,32 18.43,32.79 19.29,32.79 20.09,31.99 20.09,30.39 20.66,29.83 20.94,29.83 v1(21.27,30.16) 21.34,30.23 21.9,30.23 22.03,30.36 U14.30
  BOTTOM w0.095: R121.1 v1(21.27,30.16)
  BOTTOM w0.121: C138.1 P5.2
RXP: length 15.9
  TOP w0.095: U14.31 22.02,29.86 21.93,29.95 21.68,29.95 21.53,29.79 21.53,29.46 v1(21.27,29.21) 20.94,29.55 20.54,29.55 19.81,30.28 19.81,31.88 19.18,32.51 18.54,32.51 17.75,31.72 16.52,31.72 15.72,32.52 15.72,34.04 15.47,34.29 P5.1
  BOTTOM w0.095: R120.1 v1(21.27,29.21)
  BOTTOM w0.121: C137.1 P5.1
SPI1_CS0: length 24.7
  TOP w0.121: v1(43.32,23.61) U5.C12
  LYR4 w0.133: P9.28 50.7,6.45 49.68,6.45 49.17,6.96 49.17,8.74 46.99,10.92 46.99,13.69 45.94,14.74 45.03,14.74 43.92,15.85 43.92,21.26 43.32,21.86 v1(43.32,23.61)
SPI1_D0: length 29.4
  TOP w0.121: U5.B13 v1(42.52,22.81)
  LYR4 w0.133: 55.24,1.91 54.1,3.05 52.07,3.05 51.82,3.3 49.96,3.3 49.02,4.24 49.02,5.16 48.65,5.52 48.65,8.22 45.49,11.38 45.49,12.29 44.65,13.13 44.65,14.21 43.21,15.66 43.21,17.09 42.66,17.64 42.66,21.25 42.11,21.79 42.11,22.4 v1(42.52,22.81)
SPI1_D1: length 27.1
  TOP w0.121: v1(43.32,24.41) U5.D12
  LYR4 w0.121: 43.72,23.11 43.72,24.01 v1(43.32,24.41)
  LYR4 w0.133: 55.24,4.45 54.53,4.45 51.44,7.54 51.44,8.03 50.68,8.79 49.5,8.79 47.29,11 47.29,13.74 45.97,15.06 45.04,15.06 44.15,15.95 44.15,21.46 43.72,21.89 43.72,23.11
SPI1_SCLK: length 30
  TOP w0.121: U5.A13 v1(42.52,22.01)
  LYR4 w0.133: P9.31 56.39,3.3 52.5,3.3 51.69,4.11 51.69,4.27 50.53,5.44 49.87,5.44 48.92,6.39 48.92,8.53 45.95,11.51 45.95,12.42 45.47,12.9 45.47,14.35 45.31,14.5 44.78,14.5 43.46,15.82 43.46,17.3 42.95,17.81 42.95,21.58 v1(42.52,22.01)
SYS_5V: length 67.6
  TOP w0.203: v1(26.92,16.45) 26.92,16.19 26.57,15.84 U2.32 ; U2.22 24.26,11.31 v1(24.13,11.18) 23.86,11.45 U2.21 ; v1(22.99,19.11) 23.06,19 U2.42 ; U2.7 19.04,15.04 v1(18.8,14.8) 18.95,14.64 U2.8 ; U2.39 v1(24.26,19.11) ; v1(18.8,17.4) 19.15,17.04 U2.2
  TOP w0.381: v1(14.73,44.7) 14.35,45.09 12.45,45.09 12.32,44.96 12.32,47.62
  LYR4 w0.381: v1(14.73,44.7) 14.78,44.65 14.78,43.92 19.89,38.81 20.78,38.81 v2(21.03,38.56) 20.37,37.9 20.37,35.51 21.97,33.91 21.97,27.3 21.38,26.71 21.38,24.55 22.58,23.34 23.52,23.34 24.91,21.95 24.91,19.77 v1(24.26,19.11)
  LYR4 w0.762: v1(24.13,11.18) 23.78,10.83 23.78,8.48 27.3,4.95 P9.8
  BOTTOM w0.381: C10.2 18.99,14.61 v1(18.8,14.8) ; C8.2 C7.2 23.81,11.49 v1(24.13,11.18) ; v1(22.99,19.11) 23.24,19.11 23.5,18.86 23.5,18.35 C13.2 24.26,18.48 v1(24.26,19.11) ; U4.2 19.43,40.49 20.32,39.6 C17.1 20.57,39.12 20.95,38.73 20.95,38.63 v2(21.03,38.56)
  BOTTOM w0.762: P9.7 P9.8
  vias: v1(5.97,7.75) v1(6.6,8.89) v1(6.73,7.75) v1(13.28,13.41) v1(16.41,14.68) v1(17.07,15.49)
SYS_RESETN: length 97
  TOP w0.121: v1(12.32,49.15) 12.3,49.13 S1.4 S1.2 ; U5.A10 45.32,22.08 44.7,21.46 44.7,20.83 43.81,19.94 42.93,19.94 41.66,18.67 41.66,16.76 41.91,16.51 v1(42.42,16.51) ; U14.19 v1(25.83,34.61) ; U16.4 31.1,5.7 P9.10
  LYR3 w0.133: v1(42.42,16.51) 41.91,16 38.35,16 38.1,15.75 34.73,15.75 v1(34.29,16.19)
  LYR4 w0.133: v1(12.32,49.15) 13.72,47.75 20.57,47.75 24.63,43.69 24.63,35.81 v1(25.83,34.61) 28.39,34.61 30.28,32.71 30.28,19.1 v1(29.97,18.8) 30.48,18.29 30.48,15.75 27.62,12.89 v1(27.62,12.06) 29.31,10.38 29.31,4.98 P9.10
  BOTTOM w0.121: v1(34.29,16.19) P2.15 30.8,16.19 30.48,16.51 30.48,18.29 v1(29.97,18.8) ; v1(27.62,12.06) R14.2 C24.1 C30.1
TCT_RCT: length 6.4
  BOTTOM w0.121: P5.4 15.88,29.21 P5.5 R137.1 C141.1
TESTOUT: length 2.9
  TOP w0.121: TP3.1 51.44,21.89 U5.A3
TIMER4: length 33.6
  TOP w0.121: v1(48.12,34.01) U5.R7
  LYR3 w0.121: 47.72,35.05 47.72,34.41 v1(48.12,34.01)
  LYR3 w0.133: v1(34.04,48.26) 35.33,46.96 42.44,46.96 43.31,46.1 43.31,45.59 44.2,44.7 44.54,44.7 45.72,43.52 45.72,41.15 46.75,40.12 46.75,36.31 47.72,35.34 47.72,35.05
  LYR4 w0.133: P8.7 27.3,49.15 28.7,47.75 33.53,47.75 v1(34.04,48.26)
TIMER5: length 30.6
  TOP w0.121: v1(48.92,34.81) U5.T6
  LYR3 w0.133: v1(35.81,48.26) 36.32,47.75 43.75,47.75 46.23,45.27 46.23,41.53 48.39,39.37 48.39,35.69 48.92,35.15 v1(48.92,34.81)
  LYR4 w0.133: v1(35.81,48.26) 34.92,49.15 30.86,49.15 P8.9
TIMER6: length 36.6
  TOP w0.121: U5.U6 48.92,35.61 48.92,37.24 49.4,37.72 49.4,44.7 49.66,44.96 49.66,47.75 v1(50.16,48.26)
  LYR4 w0.133: v1(50.16,48.26) 48.9,49.53 48.9,50.8 48.13,51.56 30.99,51.56 P8.10
TIMER7: length 34.1
  TOP w0.121: v1(48.12,34.81) U5.T7
  LYR3 w0.133: v1(34.92,48.26) 35.85,47.33 42.96,47.33 44.27,46.02 44.27,45.77 45.97,44.07 45.97,41.3 48.12,39.15 v1(48.12,34.81)
  LYR4 w0.133: v1(34.92,48.26) 34.42,48.77 29.59,48.77 28.57,49.78 28.57,51.44 P8.8
TXCLK: length 6.1
  TOP w0.121: U14.20 25.33,34.67 25.67,35.01 28.45,35.01 28.61,35.16 28.61,35.16 28.85,35.39 28.85,35.4 29.01,35.56 v1(29.21,35.56)
  BOTTOM w0.121: R134.2 v1(29.21,35.56)
TXN: length 20.3
  TOP w0.095: U14.28 21.59,31.37 21.27,31.69 v1(21.27,32.07)
  LYR3 w0.102: P5.6 17.14,29.09 16.89,29.34 16.15,29.34 15.9,29.09 15.9,27.66 16.71,26.85 18.21,26.85 19.81,28.45 19.81,30.09 20.88,31.16 20.88,31.68 v1(21.27,32.07)
  BOTTOM w0.095: R123.1 v1(21.27,32.07)
  BOTTOM w0.121: P5.6 C140.1
TXP: length 17.8
  TOP w0.095: U14.29 22.03,30.86 21.81,31.09 21.28,31.09 21.27,31.1 v1(21.27,31.11)
  LYR3 w0.102: P5.3 15.6,30.76 15.6,27.53 16.59,26.54 18.34,26.54 20.12,28.32 20.12,29.96 v1(21.27,31.11)
  BOTTOM w0.095: R122.1 v1(21.27,31.11)
  BOTTOM w0.121: C139.1 P5.3
U5_H18: length 4.2
  TOP w0.121: R28.1 37.9,27.81 38.1,28.01 U5.H18
U5_R13: length 8.5
  TOP w0.121: v1(42.52,34.01) U5.R13
  LYR3 w0.121: v1(42.52,34.01) 42.92,34.41 42.92,36.46 42.71,36.66
  LYR3 w0.133: 42.71,36.66 42.26,37.12 42.26,39.22 v1(42.09,39.4)
  BOTTOM w0.133: R160.1 42.42,39.73 v1(42.09,39.4)
U5_T13: length 7.5
  TOP w0.121: v1(42.52,34.81) U5.T13
  LYR3 w0.133: v1(41.48,39.45) 41.49,39.43 41.49,39.3 42,38.8 42,36.77 42.52,36.25 v1(42.52,34.81)
  BOTTOM w0.133: v1(41.48,39.45) 41.53,39.5 R161.1
UART0_RX: length 28.4
  TOP w0.121: v1(40.92,25.21) U5.E15
  LYR4 w0.133: v1(40.92,25.21) 40.5,24.79 39.96,24.79 39.45,24.28 39.45,21.71 40.69,20.47 40.69,15.37 41.4,14.66 41.4,13.54 v1(43.61,11.33)
  BOTTOM w0.121: U15.6 53.22,11.68 52.32,12.57 50.16,12.57 49.31,11.72 44.01,11.72 v1(43.61,11.33)
UART0_TX: length 28.7
  TOP w0.121: v1(40.12,25.21) U5.E16
  LYR4 w0.133: v1(40.12,25.21) 40.01,25.21 39.19,24.39 39.19,21.59 40.41,20.37 40.41,15.01 41.17,14.26 41.17,13.14 v1(43.03,11.28)
  BOTTOM w0.121: U15.5 53.23,12.18 52.58,12.83 49.91,12.83 49.12,12.04 43.41,12.04 43.03,11.66 v1(43.03,11.28)
UART1_RXD: length 25.6
  TOP w0.121: U5.D16 40.13,24.42 v1(40.13,24.38)
  LYR4 w0.121: v1(40.13,24.38) 40.52,24 40.52,21.84 40.72,21.64
  LYR4 w0.133: v1(45.09,8.89) 44.58,9.4 44.58,11.68 42.21,14.04 42.21,14.91 41.5,15.62 41.5,20.85 40.72,21.64
  BOTTOM w0.121: P9.26 48.77,5.84 47.75,5.84 46.35,7.24 46.35,8.13 45.59,8.89 v1(45.09,8.89)
UART1_TXD: length 23.3
  TOP w0.121: v1(40.92,24.41) U5.D15
  LYR4 w0.121: 41.32,23.37 41.32,24.01 v1(40.92,24.41)
  LYR4 w0.133: 41.32,23.37 41.33,23.35 41.33,21.41 41.74,21 41.74,15.79 42.52,15.01 42.52,14.07 44.88,11.71 44.88,9.98 46.13,8.74 46.13,5.94 P9.24
UART2_RXD: length 83.9
  TOP w0.121: U5.A17 39.72,22.19 38.09,20.57 38.09,12.99 40.74,10.34 v1(40.74,10.21) 40.84,10.11 40.84,6.78 41.66,5.97 43.56,5.97 P9.22 ; v1(79.32,35.12) 78.04,36.4 J5.1
  LYR3 w0.133: v1(40.74,10.21) 41.01,10.48 46.29,10.48 47.06,9.71 54.61,9.71 54.94,10.04 54.94,10.3 55.25,10.62 55.79,10.62 57.65,12.47 68.4,12.47 80.88,24.95 80.88,33.56 v1(79.32,35.12)
UART2_TXD: length 85.8
  TOP w0.121: J5.2 78.78,34.4 v1(79.07,34.11) ; P9.21 43.81,3.17 43.81,4.83 43.05,5.59 41.53,5.59 40.51,6.6 40.51,9.78 v1(40.03,10.26) 37.85,12.45 37.85,20.7 39.32,22.17 39.32,22.81 U5.B17
  LYR3 w0.133: v1(79.07,34.11) 80.64,32.54 80.64,25.05 68.3,12.71 56.44,12.71 53.68,9.94 47.28,9.94 46.51,10.72 40.49,10.72 v1(40.03,10.26)
UART4_RXD: length 41.6
  TOP w0.121: v1(37.08,36.7) 37.21,36.58 37.21,36.35 37.52,36.04 37.52,36 38.7,34.81 39.32,34.81 U5.T17
  LYR4 w0.133: v1(33.15,6.48) 33.15,16.38 34.29,17.53 34.29,23.11 34.54,23.37 34.54,35.31 35.37,36.13 36.46,36.13 37.03,36.7 v1(37.08,36.7)
  BOTTOM w0.121: v1(33.15,6.48) 33.15,5.91 33.66,5.4 33.66,3.17 P9.11
UART4_TXD: length 44.2
  TOP w0.121: U5.U17 39.32,35.61 38.68,35.61 38.35,35.94 38.35,36.06 38.2,36.21 v1(38.2,36.22) ; P9.13 33.66,3.17 33.66,5.08 v1(32.26,6.48)
  LYR4 w0.121: v1(38.2,36.22) 38.19,36.22
  LYR4 w0.133: v1(32.26,6.48) 32.26,16.51 33.78,18.03 33.78,23.37 34.04,23.62 34.04,35.93 36.18,38.07 36.88,38.07 37.49,37.47 37.49,36.65 37.92,36.22 38.19,36.22
USB0_DM: length 42.2
  TOP w0.114: v1(10.79,43.26) 10.79,43.27 10.79,43.56 10.92,43.69 11.34,43.69 11.66,43.37 11.66,42.49 12.24,41.91 U10.2 12.8,41.91 13.02,42.13 13.02,42.69 13.13,42.8 15.49,42.8 21.44,36.86 31.25,36.86 31.68,36.42 33.64,36.42 34.52,35.55 34.52,35.28 34.69,35.11 34.96,35.11 35.18,34.89 35.18,34.67 35.36,34.49 35.57,34.49 36.07,34 36.07,32.94 36.78,32.23 37.03,32.23 37.18,32.38 37.45,32.38 37.59,32.23 37.92,32.23 38.07,32.38 38.4,32.38 38.65,32.13 38.8,32.13 U5.N18
  BOTTOM w0.114: P4.2 10.58,43.48 v1(10.79,43.26)
USB0_DP: length 42.2
  TOP w0.114: v1(10.79,44.07) 10.9,43.97 11.46,43.97 11.94,43.49 11.94,42.61 12.14,42.41 U10.1 12.7,42.53 12.7,42.88 12.9,43.08 15.61,43.08 21.55,37.13 31.37,37.13 31.8,36.7 33.76,36.7 36.35,34.11 36.35,33.06 36.75,32.66 38.51,32.66 38.76,32.41 39.32,32.41 U5.N17
  BOTTOM w0.114: v1(10.79,44.07) 10.79,44.02 10.54,43.76 5.9,43.76 5.52,44.13 P4.3
USB0_ID: length 48.7
  TOP w0.121: v1(15.62,41.91) 14.61,40.89 12.71,40.89 12.58,41.02 U10.3 ; U5.P16 v1(40.12,33.21)
  LYR3 w0.133: v1(40.12,33.21) 40.49,33.58 40.49,35.03 40.25,35.26 40.15,35.26 39.91,35.5 38.14,35.5 37.49,36.14 37.49,38.84 36.63,39.7 35.51,39.7 34.85,40.36 31.17,40.36 30.3,41.22 26.36,41.22 25.76,41.83 15.7,41.83 v1(15.62,41.91)
  BOTTOM w0.121: P4.4 5.49,44.78 5.87,45.16 13.36,45.16 15.54,42.98 15.54,41.99 v1(15.62,41.91)
USB1_DM: length 54.2
  TOP w0.114: v1(36.22,34.98) 36.14,34.9 36.14,34.74 36.33,34.54 37.17,34.54 37.98,33.73 38.8,33.73 U5.R18
  LYR3 w0.127: v1(36.22,34.98) 36.22,35.13 35.97,35.38 35.97,35.79 35.51,36.25 34.62,36.25 33.3,37.57 23.72,37.57 22.07,35.92 22.07,27.92 21.26,27.1 21.26,24.18 18.26,21.18 16.99,21.18 14,18.19 14,16.43 14.42,16 14.78,16 15.06,16.28 v1(15.06,16.36)
  BOTTOM w0.114: P3.2 10.28,12.17 10.92,11.53 12.2,11.53 13.94,13.26 13.94,13.54 13.72,13.76 U9.2 13.72,14.45 13.87,14.61 14.51,14.61 14.68,14.77 14.68,16.08 14.96,16.36 v1(15.06,16.36)
USB1_DP: length 54.3
  TOP w0.114: v1(36.86,34.98) 37.13,34.98 38.1,34.01 39.24,34.01 39.64,33.61 U5.R17
  LYR3 w0.127: v1(36.86,34.98) 36.73,35.1 36.68,35.1 36.53,35.25 36.27,35.51 36.27,35.92 35.64,36.55 34.75,36.55 33.43,37.87 23.6,37.87 21.77,36.04 21.77,28.04 20.95,27.23 20.95,24.31 18.14,21.49 16.87,21.49 13.69,18.31 13.69,16.3 14.24,15.75 v1(15.14,15.75)
  BOTTOM w0.114: v1(15.14,15.75) 14.96,15.57 14.96,14.66 14.63,14.33 14.3,14.33 14.22,14.24 U9.1 14.22,13.15 12.32,11.25 10.72,11.25 P3.3
USB1_DRVVBUS: length 62.3
  TOP w0.121: U5.F15 v1(40.92,26.01)
  LYR3 w0.133: v1(39.85,8.41) 39.66,8.22 36.29,8.22 36.24,8.17 29.48,8.17 28.88,8.76 22.23,8.76 21.9,9.08 13.53,9.08 11.43,6.99 2.67,6.99 v1(2.29,6.6)
  LYR4 w0.121: 38.93,24.64 40.3,26.01 v1(40.92,26.01)
  LYR4 w0.133: v1(39.85,8.41) 39.5,8.76 39.5,11.3 40.59,12.4 40.59,14.25 40.13,14.71 40.13,18.8 39.52,19.41 39.52,20.73 38.93,21.32 38.93,24.64
  BOTTOM w0.121: U8.4 2.96,7.03 R53.1 2.67,6.99 v1(2.29,6.6)
USB1_ID: length 1.9
  TOP w0.121: v1(39.32,33.21) 39.37,33.16 U5.P17
  BOTTOM w0.121: R49.2 39.05,33.97 39.32,33.71 v1(39.32,33.21)
USB1_OCN: length 65.1
  TOP w0.121: v1(40.08,34.86) 40.11,34.83 40.11,34.82 U5.T16
  LYR3 w0.121: 39.78,35.2 37.95,35.2 36.58,36.58 36.58,37.33 36.61,37.36 36.61,37.81
  LYR3 w0.133: 36.61,37.81 36.32,38.1 35.2,38.1 34.38,38.93 21.81,38.93 21.72,39.01 16.97,39.01 16.88,38.93 v1(12.93,38.93) ; 39.78,35.2 40.08,34.9 v1(40.08,34.86)
  LYR4 w0.133: v1(1.78,15.62) 1.93,15.47 7.62,15.47 13.26,21.11 13.26,38.6 v1(12.93,38.93)
  BOTTOM w0.121: v1(1.78,15.62) 2.16,15.24 R52.2 2.54,14.65 2.96,14.22 U8.5
USB1_PWR: length 9.8
  LYR3 w0.381: v1(12.7,16.51) 9.27,16.51 7.37,14.61 v1(5.97,14.61)
  BOTTOM w0.254: v1(12.7,16.51) 13.08,16.51 14.22,15.38 U9.6
USB1_VBUS: length 55.1
  TOP w0.305: v1(36.2,37.47) 36.58,37.08 36.58,36.5 37.18,35.9 37.18,35.83 38.59,34.41 U5.T18
  LYR3 w0.381: v1(36.2,37.47) 36.12,37.54 35.15,37.54 34.16,38.53 23.29,38.53 21.54,36.78 v1(19.63,36.78)
  LYR4 w0.381: v1(19.63,36.78) 19.63,35.48 20.7,34.42 20.7,25.4 v1(20.32,25.02)
  BOTTOM w0.381: FB8.1 3.94,17.78 6.48,20.32 15.11,20.32 16.26,21.46 17.65,21.46 20.32,24.13 v1(20.32,25.02)
USB_DC: length 26.5
  TOP w0.254: v1(14.73,42.14) 14.66,42.14 14.38,42.41 U10.6
  LYR3 w0.381: v1(14.73,42.14) 14.73,42.04 15.49,41.27 25.63,41.27 26.62,40.29 28.28,40.29 28.61,40.61 30.33,40.61 31.09,39.85 34.72,39.85 35.31,39.27 36.25,39.27 36.86,38.66 v1(36.86,38.51)
  BOTTOM w0.381: R159.1 37.01,38.35 v1(36.86,38.51)
  vias: v1(19.3,11.4) v1(19.25,10.82) v1(19.81,11.05) v2(11.18,42.16) v2(11.2,41.15) v2(11.94,41.12)
USR0: length 25.9
  TOP w0.121: U5.V15 41.32,36.35 39.87,37.8 38.02,37.8 37.34,38.48 37.34,38.61 36.96,38.99 34.9,38.99 33.99,38.07 26.21,38.07 24.64,39.65 24.64,40.03 22.63,42.04 R76.1 21.46,42.55 20.32,42.55 19.94,42.93 Q1.2
USR1: length 30.5
  TOP w0.121: U5.U15 41.72,35.61 41.72,36.33 39.85,38.2 38.13,38.2 37.08,39.24 34.72,39.24 33.81,38.33 26.34,38.33 24.92,39.75 24.92,40.16 22.73,42.34 22.73,44.7 R77.1 21.46,45.97 20.19,45.97 19.94,45.72 Q1.5
USR2: length 31.6
  TOP w0.121: Q2.2 17.27,42.67 v1(17.53,42.42) 18.54,41.4 R78.1 ; U5.T15 40.91,34.82 v1(40.91,34.82)
  LYR3 w0.133: v1(17.53,42.42) 17.88,42.06 27.9,42.06 27.9,42.07 28.24,42.07 28.24,42.06 29.9,42.06 31.32,40.64 34.98,40.64 35.53,40.08 36.63,40.08 37.82,38.89 37.82,37.67 38.4,37.08 38.4,36.78 39.39,35.8 40.09,35.8 40.91,34.98 v1(40.91,34.82)
USR3: length 28.8
  TOP w0.121: Q2.5 17.27,44.2 17.4,44.07 18.19,44.07 18.39,43.87 18.39,43.23 19.08,42.55 19.68,42.55 20.57,41.66 R79.1 21.18,41.4 21.26,41.48 22.81,41.48 24.16,40.13 24.16,39.71 26.05,37.82 34.11,37.82 34.45,38.16 35.92,38.16 35.95,38.13 36.66,38.13 36.69,38.11 37.21,38.11 37.8,37.52 39.8,37.52 40.52,36.8 U5.V16
VDCDC1:
  vias: v1(20.07,9.91) v1(20.7,9.91)
VIO: length 22.4
  TOP w0.121: U2.18 22.66,11.67 22.16,11.18 v1(22.1,11.18) ; v1(30.25,9.25) 30.68,8.81 31.71,8.81 32.4,8.12 U16.5
  LYR3 w0.133: v1(22.1,11.18) 22.99,11.18 23.75,10.41 28.88,10.41 30.05,9.25 v1(30.25,9.25)
  BOTTOM w0.121: v1(22.1,11.18) 22.1,12.57 21.72,12.95 21.21,12.95 20.45,13.72 18.14,13.72 16.38,15.47 R7.2
VLDO1: length 4.5
  TOP w0.203: 19.05,16.64 U2.3
  TOP w0.254: v1(18.29,16.76) 18.41,16.64 19.05,16.64
  BOTTOM w0.381: v1(18.29,16.76) 17.65,16.13 17.4,16.13 17.4,17.91
VREFP_ADC: length 7.7
  TOP w0.121: 45.59,21.72 45.72,21.84 45.72,22.81
  TOP w0.254: 45.72,22.81 U5.B9
  TOP w0.305: 45.29,21.42 45.59,21.72
  TOP w0.381: 45.29,21.42 45.21,21.34 45.21,20.65 44.1,19.54 R27.2 44.1,18.32 C33.1 C31.1 C32.1
VRTC: length 42.4
  TOP w0.254: v1(48.12,24.41) U5.D7
  LYR3 w0.381: v1(16.89,20.32) 20.57,20.32 20.95,20.7 25.53,20.7 27.3,22.48 33.15,22.48 35.18,20.45 37.44,20.45 37.44,20.45 37.59,20.45 38.38,19.66 46.08,19.66 47.31,20.89 v1(47.31,20.95)
  BOTTOM w0.178: R26.1 49.82,19.18 49.69,19.3 49.69,20.67 49.4,20.95 v1(49.21,20.95)
  BOTTOM w0.381: C105.1 v1(47.31,20.95) ; R5.2 C16.1 15.11,18.97 16.46,20.32 v1(16.89,20.32)
WAKEUP: length 63.4
  TOP w0.121: v1(21.08,11.17) 21.08,11.18 20.66,11.6 U2.13 ; U5.C5 v1(49.72,23.61)
  LYR3 w0.133: v1(58.42,11.43) 55.98,8.99 46.63,8.99 45.97,9.65 41.71,9.65 41.35,9.3 34.44,9.3 33.83,8.69 29.84,8.69 29.13,9.4 24.13,9.4 22.86,10.67 21.58,10.67 v1(21.08,11.17)
  LYR4 w0.133: v1(58.42,11.43) 58.42,16.51 54.99,19.94 54.74,19.94 53.47,21.21 50.61,21.21 49.28,22.55 49.28,23.16 v1(49.72,23.61)
  BOTTOM w0.121: v1(49.72,23.61) 50.12,23.21 50.12,22.54 50.16,22.5 R26.2
WP: length 9.2
  BOTTOM w0.121: U7.5 28.09,22.86 27.43,23.51 25.81,23.51 25.55,23.26 25.55,22.54 25.43,22.42 R156.2 24.64,22.42 24.07,22.99 21.84,22.99 TP4.1
XDMA_EVENT_INTR0: length 10.7
  BOTTOM w0.121: P2.17 34.23,17.46 34.92,16.76 34.92,15.37 36,14.29 39.38,14.29 39.57,14.1 40.39,14.1 40.64,13.84 R18.2
YEL_C: length 3.2
  TOP w0.381: P5.11 4.32,27.03 v1(4.32,27.94)
  BOTTOM w0.381: R130.2 v1(4.32,27.94)
YELA: length 28.5
  TOP w0.254: U14.2 v1(23.83,27.43)
  BOTTOM w0.254: R135.1 5.21,26.54 5.84,25.91 6.6,25.91 7.05,26.35 7.05,27.62 7.49,28.07 C166.1 C164.1 9.14,28.07 10.67,26.54 11.73,26.54 14.66,23.62 17.91,23.62 21.21,26.92 23.32,26.92 v1(23.83,27.43)
  BOTTOM w0.381: P5.12 4.88,26.34 R135.1
ZQ: length 2.5
  TOP w0.121: v1(66.3,22.36) U12.L8
  BOTTOM w0.121: v1(66.3,22.36) 66.7,21.96 R99.2
N21757673: length 4.3
  BOTTOM w0.121: U4.4 16.89,40.26 16.13,39.5 R10.1 C19.1 R11.2
N21769115: length 5.9
  TOP w0.121: R75.2 76.83,46.35 77.34,45.85 77.34,45.11 S2.1 S2.3
N22155575: length 7
  TOP w0.121: v1(40.92,33.21) U5.P15
  LYR3 w0.133: v1(40.92,35.59) 40.92,35.53 41.31,35.14 41.31,33.6 v1(40.92,33.21)
  BOTTOM w0.381: R159.2 39.09,38.35 40.64,36.8 40.64,35.86 v1(40.92,35.59)
N22248684: length 1.5
  TOP w0.121: R167.1 38.48,42.8 39.18,42.1 Y4.3
N22287501: length 12.7
  TOP w0.121: v1(36.7,48.26) 37.08,47.88 40.64,47.88 40.97,47.55 U3.4
  BOTTOM w0.121: R162.1 30.48,48.26 30.99,48.77 36.2,48.77 v1(36.7,48.26)
N22287555: length 18.9
  TOP w0.121: v1(41.72,34.01) U5.R14 ; U3.2 40.32,44.13 40.13,43.94 37.67,43.94 36.07,42.34 36.07,40.64 38.05,38.66 39.98,38.66 v1(40.34,39.01)
  LYR3 w0.121: v1(41.72,34.01) 42.12,34.41 42.12,35.68
  LYR3 w0.133: v1(40.34,39.01) 40.84,38.51 40.84,37.36 42.12,36.09 42.12,35.68
N22420400: length 9.6
  TOP w0.203: U2.4 18.91,16.24 18.8,16.13 19.09,15.84 U2.5
  TOP w0.381: TP5.1 15.16,10.67 16.42,11.92 16.42,13.85 18.69,16.13 18.8,16.13
N22420444: length 10.1
  TOP w0.203: U2.6 18.67,15.44 16.89,13.67 16.89,11.76 16.1,10.97 16.1,9.5 TP6.1
N22420447: length 4.1
  TOP w0.203: U2.11 19.28,13.44 18.59,12.75 18.59,12.14 17.27,10.82 TP7.1
N22488252: length 24.6
  TOP w0.121: U5.E17 39.32,25.21 38.17,25.21 37.36,24.4 36.43,24.4 36.05,24.78 35.39,24.78 34.16,23.55 34.16,19.58 33.35,18.77 32.51,18.77 30.99,20.29 30.99,20.45 27.81,23.62 25.02,23.62 TP9.1
N22648410: length 8.6
  BOTTOM w0.121: Y2.2 54.61,43.43 54.61,42.04 54.23,41.66 52.83,41.66 R17.1 52.32,42.16 C25.1 51.68,42.15 U17.1
N22648422: length 8.2
  BOTTOM w0.121: Y2.1 54.86,40.77 54.48,41.15 52.83,41.15 R17.2 52.45,41.02 C26.1 51.06,41.65 U17.2
N22649826: length 1.5
  BOTTOM w0.121: R171.2 49.27,41.15 U17.3
N22650321: length 3.4
  BOTTOM w0.121: U17.6 45.98,41.15 45.72,40.89 45.72,40.51 45.47,40.26 R172.2 R174.1
N22650344: length 2.4
  BOTTOM w0.121: U17.7 45.33,41.65 R175.2 R173.1
N22650388: length 5.3
  TOP w0.121: U5.V10 45.21,36.12 45.21,37.59 45.59,37.97 v1(45.59,38.99)
  BOTTOM w0.121: U17.5 46.11,40.65 45.97,40.51 45.97,40.01 45.59,39.62 v1(45.59,38.99)

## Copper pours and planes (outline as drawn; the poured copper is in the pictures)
DGND on TOP (solid shape): 5.84,9.14 2.03,9.14 2.03,12.95 5.84,12.95
DGND on TOP: 58.39,35.38 67.36,35.38 70.59,32.16 70.59,15.75 69.75,14.91 62.38,14.91 58.27,10.79 55.63,10.79 55.3,11.13 55.3,11.71 55.5,11.91 55.98,11.91 56.21,12.14 56.21,13.56 56.34,13.69 56.87,13.69 58.85,15.67 58.85,15.98 59.13,16.26 66.78,16.26 68,17.48 68,31.09 64.74,34.34 59.59,34.34 59.49,34.24 58.67,34.24 58.19,34.72 58.19,35.18
DGND on TOP: 21.97,27.69 27.94,27.69 28.83,26.8 28.83,24.38 28.45,24 21.59,24 21.08,24.51 21.08,26.8
DGND on TOP: 24.05,9.19 27.1,9.19 27.2,9.09 27.2,6.93 27.03,6.76 25.53,6.76 24.97,7.32 24.28,7.32 23.9,7.7 23.9,9.04
DGND on TOP: 13.72,20.7 18.41,20.7 18.54,20.57 18.54,19.18 17.91,18.54 16.76,18.54 16.26,18.03 16.26,16.26 16,16 13.84,16 13.46,15.62 12.19,15.62 12.06,15.75 12.06,19.05
DGND on TOP: 41.66,43.69 41.91,43.43 41.91,39.62 41.66,39.37 40.01,39.37 39.62,38.99 37.97,38.99 36.7,40.26 36.7,42.67 37.72,43.69
DGND on TOP: 27.76,21.84 28.96,21.84 30.73,20.07 30.73,19.68 32.26,18.16 32.26,15.77 32,15.52 28.47,15.52 28.3,15.7 28.3,16.64 28.4,16.74 29.39,16.74 29.67,17.02 29.67,18.11 27.58,20.19 27.58,21.67
DGND on BOTTOM: 27.18,27.56 28.45,27.56 28.96,27.05 28.96,24.64 28.45,24.13 22.35,24.13 21.46,25.02 21.46,26.29 21.84,26.67 26.29,26.67 26.43,26.81 26.43,27.24 26.7,27.51 27.13,27.51
DGND on BOTTOM: 19.56,16.07 19.56,15.75 19.89,15.42 20.65,15.42 20.95,15.11 20.95,13.39 21.08,13.26 21.08,13.21 22.54,13.21 23.11,13.78 24.13,13.78 24.38,14.03 24.38,14.67 25.15,14.67 25.15,14.41 25.4,14.16 26.04,14.16 26.29,14.41 26.29,16.59 26.09,16.79 25.3,16.79 25.15,16.64 25.15,15.81 24.38,15.81 24.38,16.56 24.18,16.76 23.47,16.76 23.24,16.54 23.24,15.81 22.48,15.81 22.48,16.54 22.28,16.74 21.46,16.74 21.34,16.61 21.34,15.81 20.57,15.81 20.57,16.46 20.37,16.66 19.63,16.66 19.56,16.59 19.56,16.43 19.56,16.43 19.56,16.07
DGND on BOTTOM: 52.25,36.96 66.73,36.96 70.05,33.63 70.05,31.24 71.6,29.69 71.6,13.64 71.02,13.06 62.23,13.06 60.2,15.09 56.87,15.09 55.6,16.36 52.53,16.36 51.77,17.12 51.77,19.46 52.37,19.46 52.7,19.13 54.15,19.13 57.23,16.05 67.74,16.05 68.25,16.56 68.25,17.73 68.15,17.83 68.15,18.21 68.63,18.69 68.63,25.78 68.61,25.81 69.11,26.31 69.29,26.31 69.29,27.79 68.66,28.42 68.66,31.06 68.73,31.14 68.73,31.52 67.87,32.38 65.86,32.38 63.96,34.29 53.01,34.29 51.89,35.41 51.89,36.6
DGND on BOTTOM: 32.77,29.24 33.07,29.24 33.35,29.51 33.35,30.07 33.43,30.15 34.04,30.15 34.11,30.07 34.11,24.03 33.78,23.7 33.02,23.7 32.64,24.08 32.64,26.37 32.74,26.47 32.74,29.21
DGND on BOTTOM: 41.27,30.48 41.4,30.61 41.4,30.99 41.91,30.99 41.91,30.61 42.16,30.35 42.16,29.72 41.91,29.46 41.91,29.08 41.27,29.08
DGND on BOTTOM: 23.85,34.01 24.64,34.01 26.52,32.13 26.52,28.4 26.37,28.24 23.77,28.24 23.65,28.37 23.65,33.81
